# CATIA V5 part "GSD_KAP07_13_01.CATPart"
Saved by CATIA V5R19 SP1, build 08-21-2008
Part number: GSD_NEAR_01
Definition: Beispielmodell für die Funktion Nahe / Near.
Description: CATIA V5 Flächenmodellierung  Copyright 2009 Maik Hertha IT Consultants
Bounding box of the stored display mesh (mm): x -118.392 to 45.702, y 19.124 to 80.975, z 13.956 to 57.238
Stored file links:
  \GSD_BUCH_UEBUNG\GSD_KAP07_13_01.CATPart
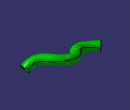
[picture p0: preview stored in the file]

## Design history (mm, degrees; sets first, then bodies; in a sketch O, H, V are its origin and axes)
AxisSystem1 "Absolute Axis System": origin (0, 0, 0), X (1, 0, 0), Y (0, 1, 0), Z (0, 0, 1)
Set1 "Near Support"
  Plane1: type Equation, A 0, B 1, C 0, Length -20
  Point1: type OnPlane, Support Plane1, Direction (-1, 0, 0), H -20, V 20
  Plane2: type Equation, A 0, B 0, C 1, Length -20
  Sketch1 on Plane1, origin (20, -20, 20), H (-1, 0, 0), V (0, 0, 1)
    spline S1 through (-28.6222, 7.5739) (16.6598, 27.2154) (74.1032, 14.2934) (131.2878, 3.9557)
  Sketch2 on Plane2, origin (20, -20, -20), H (1, 0, 0), V (0, 1, 0)
    spline S1 through (-139.2371, 93.2107) (-123.9174, 75.5754) (-83.9302, 69.0919) (-67.5719, 84.3931) (-34.0762, 87.2458) (-10.9667, 62.6083) (19.9324, 49.1226)
  Combine1: Curve1 Sketch1, Curve2 Sketch2
  Sweep1: type Circle, Guide Combine1, Radius 10
Set2 "Near with Extremum"
  DatumSurface1: linked copy from another document
Body1 (main body)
